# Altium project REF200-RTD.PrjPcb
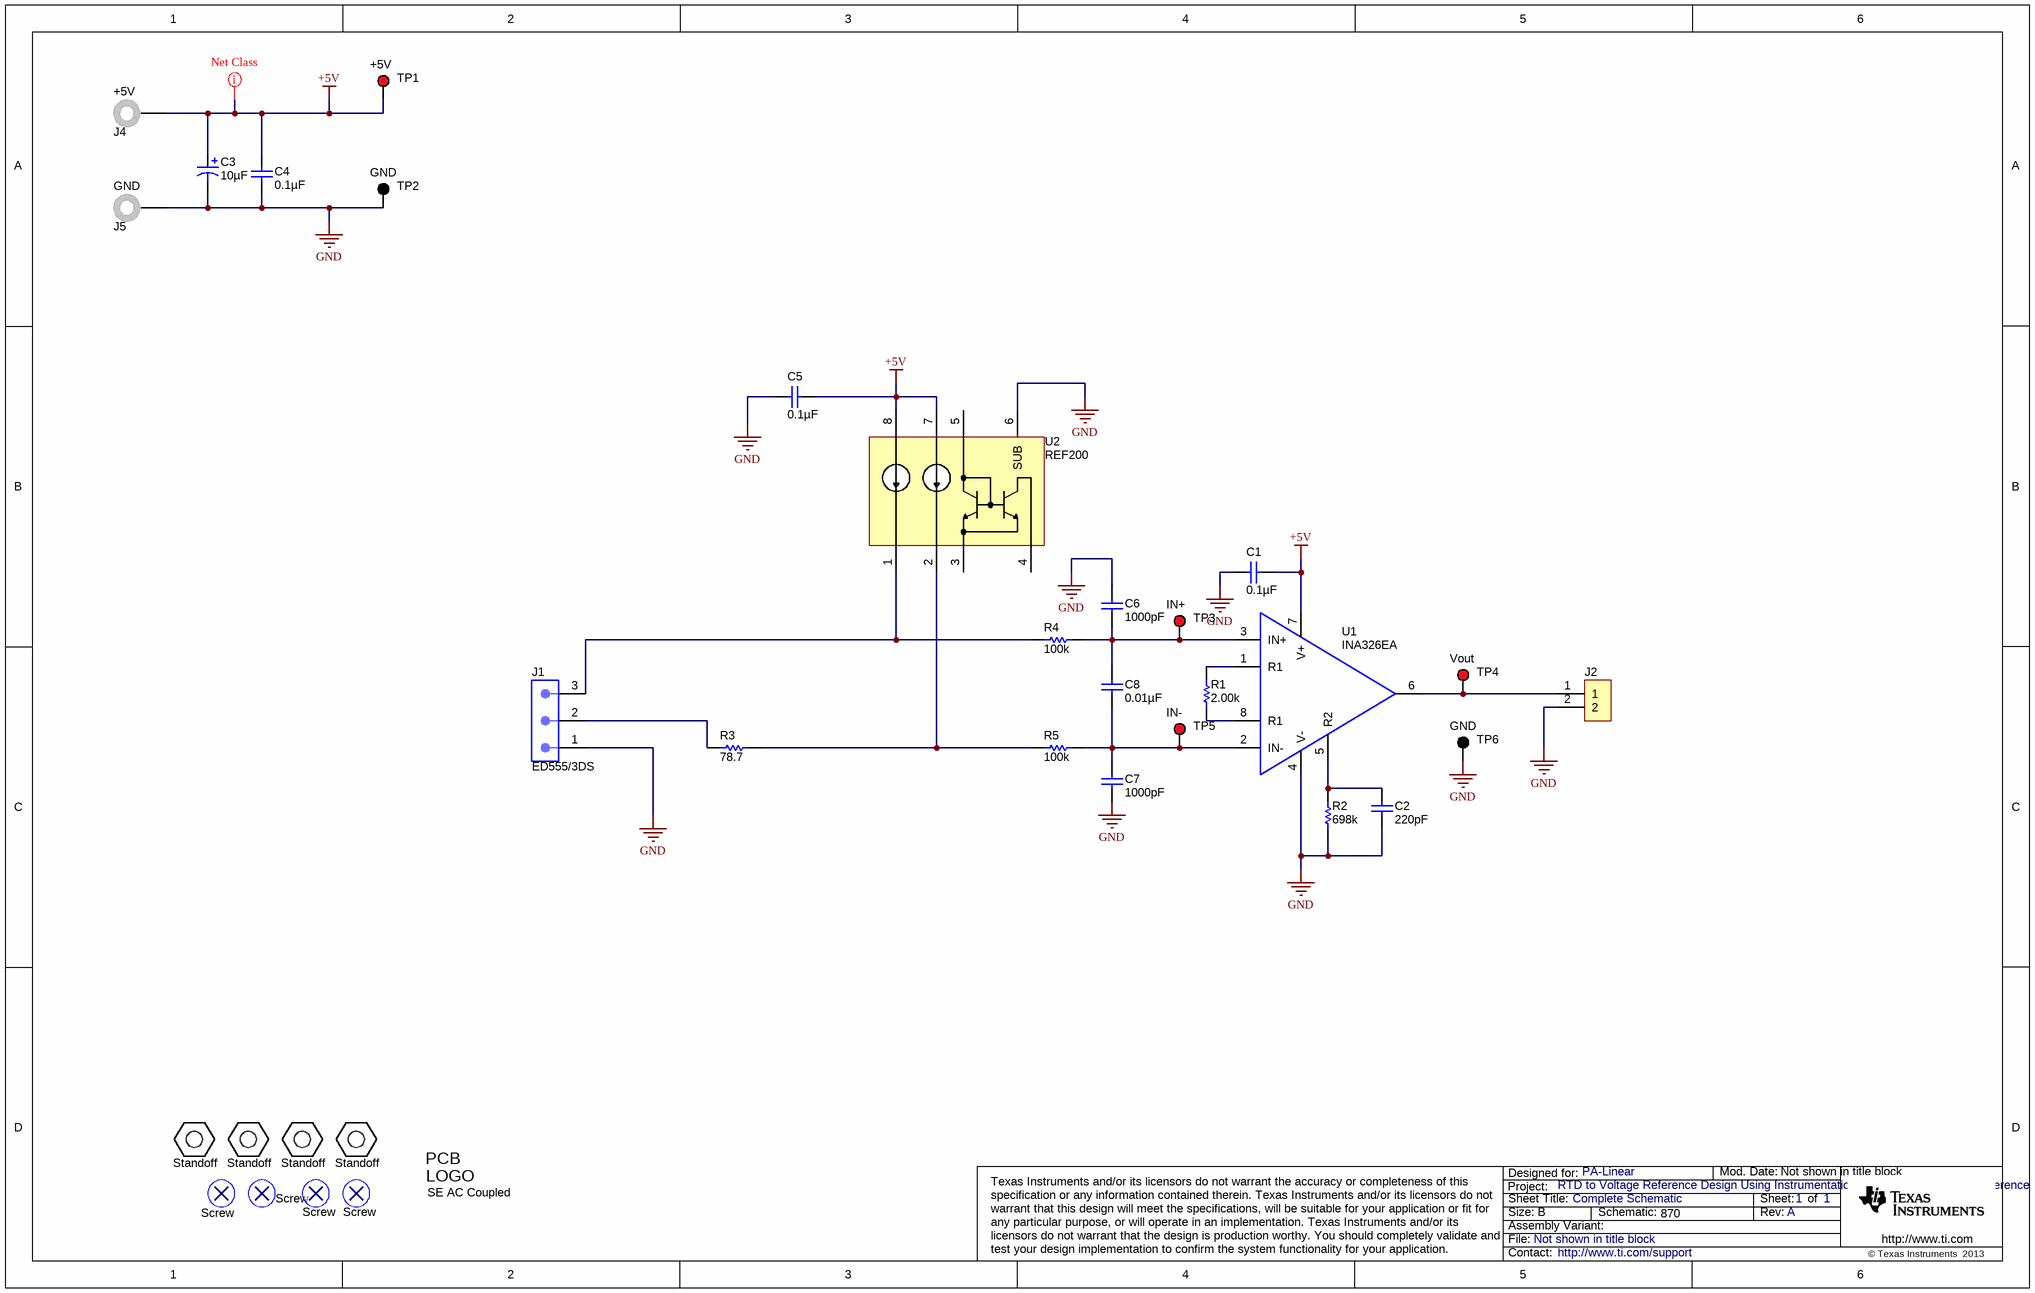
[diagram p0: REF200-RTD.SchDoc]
TechSupport: http://www.ti.com/support; SCH_Rev: A; PRJ_Title: RTD to Voltage Reference Design Using Instrumentation Amplifier and Current Reference; PRJ_Customer: PA-Linear; CopyrightYear: 2013
1 sheet, 34 parts. Net scope: global (net labels, ports and power ports of the same name join across sheets).
Board file: REF200-RTD.PcbDoc

## Sheet REF200-RTD.SchDoc: Complete Schematic
size B; Date: Not shown in title block; ApprovedBy: Not shown in title block; CheckedBy: Not shown in title block; Author: Not shown in title block; CompanyName: Not shown in title block; DrawnBy: Not shown in title block; Engineer: Not shown in title block; Organization: Not shown in title block; Address1: Not shown in title block; Address2: Not shown in title block; Address3: Not shown in title block; Address4: Not shown in title block; DocumentNumber: 1; Revision: Use project parameter SCH_Rev; SheetNumber: 1; SheetTotal: 1; PageSetup: Record=PageOptions¦CenterHorizontal=True¦CenterVertical=True¦PrintScale=0.69¦XCorrection=1.00¦YCorrection=1.00¦PrintKind=0¦BorderSize=5000000¦LeftOffset=0¦BottomOffset=0¦Orientation=2¦PaperLength=1000¦PaperWidth=1000¦Scale=100¦PaperSource=15¦PrintQuality=600¦MediaType=1¦DitherType=10¦PrintScaleMode=1¦PaperKind=Letter

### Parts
C1  ValueDisplayed: 0.1µF  [0603]  (hidden comment: 06033D104KAT2A)
C2  ValueDisplayed: 220pF  [0603]  (hidden comment: GRM1885C1H201JA01D)
C3  ValueDisplayed: 10µF  [7343-43]  (hidden comment: 293D106X9050E2TE3)
C4  ValueDisplayed: 0.1µF  [0603]  (hidden comment: 06033D104KAT2A)
C5  ValueDisplayed: 0.1µF  [0603]  (hidden comment: 06033D104KAT2A)
C6  ValueDisplayed: 1000pF  [0603]  (hidden comment: 06031C102JAT2A)
C7  ValueDisplayed: 1000pF  [0603]  (hidden comment: 06031C102JAT2A)
C8  ValueDisplayed: 0.01µF  [0603]  (hidden comment: 06031C103JAT2A)
J1  ED555/3DS  [Terminal Block 3.5mm 3 pos]
J2  Used in BOM report  [TERMINAL BLOCK 3.5MM 2 POS]  (value not drawn)
J4  +5V  [JACK NON-INSULATED .218"]
J5  GND  [JACK NON-INSULATED .218"]
R1  ValueDisplayed: 2.00k  [0603]  (hidden comment: CPF0603B2K0E)
R2  ValueDisplayed: 698k  [0603]  (hidden comment: CRCW0603698KFKEA)
R3  ValueDisplayed: 78.7  [0805_HV]  (hidden comment: CRCW080578R7FKEA)
R4  ValueDisplayed: 100k  [0603]  (hidden comment: CPF0603B100KE)
R5  ValueDisplayed: 100k  [0603]  (hidden comment: CPF0603B100KE)
TIPD191  SE AC Coupled  [TI_Symbol_Overlay_Small]  (no BOM)
TP1  +5V  [Keystone5005]
TP2  GND  [Keystone5006]
TP3  IN+  [Keystone5005]
TP4  Vout  [Keystone5005]
TP5  IN-  [Keystone5005]
TP6  GND  [Keystone5006]
U1  INA326EA  [VSSOP-8 (DGK) low density]
U2  REF200  [SOIC-8 (D) low density]
U3  Standoff  [MHOLE1]
U4  Standoff  [MHOLE1]
U5  Standoff  [MHOLE1]
U6  Standoff  [MHOLE1]
U7  Screw  (mechanical)
U8  Screw  (mechanical)
U9  Screw  (mechanical)
U10  Screw  (mechanical)

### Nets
+5V: C1.1 C3.1(+) C4.1 C5.1 J4.1 TP1.1 U1.7(V+) U2.7(I2_High) U2.8(I1_High)
GND: C1.2 C2.2 C3.2(-) C4.2 C5.2 C6.1 C7.2 J1.1 J2.2 J5.1 R2.1 TP2.1 TP6.1 U1.4(V-) U2.6(SUB)
NetC2_1: C2.1 R2.2 U1.5(R2)
NetC6_2: C6.2 C8.1 R4.2 TP3.1 U1.3(IN+)
NetC7_1: C7.1 C8.2 R5.2 TP5.1 U1.2(IN-)
NetJ1_2: J1.2 R3.1
NetJ1_3: J1.3 R4.1 U2.1(I1_Low)
NetJ2_1: J2.1 TP4.1 U1.6(OUT)
NetR1_1: R1.1 U1.8(R1)
NetR1_2: R1.2 U1.1(R1)
NetR3_2: R3.2 R5.1 U2.2(I2_Low)

Not connected (* = marked no-connect by the designer): U2 3(Mirror_Common) 4(Mirror_Out) 5(Mirror_In)

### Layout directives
net class Power: +5V

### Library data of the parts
C1 C4 C5 = 06033D104KAT2A: CAP, CERM, 0.1 µF, 25 V, +/- 10%, X5R, 0603; Manufacturer: AVX; Polarized: N; CompType: Capacitor; Value: 0.1uF; U/M: EA; Cap_F: 0.0000001; Tolerance_%: 10; ESR_ohm: 0.048; Value1: 0.048 ohm; VDC_V: 25; Value2: 25V; IRMS_A: 0.53; TaMin_C: -55; TaMax_C: 85
C2 = GRM1885C1H201JA01D: CAP, CERM, 200 pF, 50 V, +/- 5%, C0G/NP0, 0603; Manufacturer: MuRata; Polarized: N; CompType: Capacitor; Value: 200pF; U/M: EA; Cap_F: 0.0000000002; Tolerance_%: 5; Value1: Unknown; VDC_V: 50; Value2: 50V; TaMin_C: -55; TaMax_C: 125
C3 = 293D106X9050E2TE3: CAP, TA, 10 µF, 50 V, +/- 10%, 0.8 ohm, SMD; Manufacturer: Vishay-Sprague; Polarized: Y; CompType: Capacitor; Value: 10uF; U/M: EA; Cap_F: 0.00001; Tolerance_%: 10; Value1: 0.8 ohm; VDC_V: 50; Value2: 50V; ESR_ohm: 0.8; IRMS_A: 0.45; TaMin_C: -55; TaMax_C: 125; Cap_Case: E
C6 C7 = 06031C102JAT2A: CAP, CERM, 1000 pF, 100 V, +/- 5%, X7R, 0603; Manufacturer: AVX; Polarized: N; CompType: Capacitor; Value: 1000pF; U/M: EA; Cap_F: 0.000000001; Tolerance_%: 5; ESR_ohm: 0.276; Value1: 0.276 ohm; VDC_V: 100; Value2: 100V; TaMin_C: -55; TaMax_C: 125
C8 = 06031C103JAT2A: CAP, CERM, 0.01 µF, 100 V, +/- 5%, X7R, 0603; Manufacturer: AVX; Polarized: N; CompType: Capacitor; Value: 0.01uF; U/M: EA; Cap_F: 0.00000001; Tolerance_%: 5; ESR_ohm: 0.098; Value1: 0.098 ohm; VDC_V: 100; Value2: 100V; TaMin_C: -55; TaMax_C: 125
J1 = Screw Terminal, 3 Pos, 3.5mm Spacing, Through Hole: Manufacturer: On Shore Technology Inc; SymbolVersion: use current date i.e. 2008-05-20; SymbolCreator: Use LDAP id; CompType: Used in some BOM reports.  Useful for finding later.; U/M: EA, IN, or GM
J2 = Screw Terminal, 2 pos, 3.5mm, ED555/2DS: SymbolVersion: use current date i.e. 2008-05-20; SymbolCreator: Use a-id; CompType: Used in some BOM reports.  Useful for finding later.; U/M: EA, IN, or GM
J4 J5 = Banana Jack, Solder: JACK NON-INSULATED .218"; Manufacturer: Keystone; PartNumber: 575-4; SymbolVersion: use current date i.e. 2008-05-20; SymbolCreator: Use LDAP id; CompType: Used in some BOM reports.  Useful for finding later.; U/M: EA, IN, or GM
R1 = CPF0603B2K0E: RES, 2.00 k, 0.1%, 0.063 W, 0603; Manufacturer: TE Connectivity; CompType: Resistor; Value: 2.00k; Res_ohm: 2000; Value_Code: 2k00; Tolerance_%: 0.1; Power_W: 0.063; Value2: 0.063W; VDC_V: 50; TempCo: 25 ppm/C; EIA_Code: E192; U/M: EA
R2 = CRCW0603698KFKEA: RES, 698 k, 1%, 0.1 W, 0603; Manufacturer: Vishay-Dale; CompType: Resistor; Value: 698k; Res_ohm: 698000; Tolerance_%: 1; Power_W: 0.1; Value2: 0.1W; VDC_V: 75; TempCo: 100 ppm/C; EIA_Code: E96; U/M: EA
R3 = CRCW080578R7FKEA: RES, 78.7, 1%, 0.125 W, 0805; Manufacturer: Vishay-Dale; CompType: Resistor; Value: 78.7; Value_Code: 78R7; Tolerance_%: 1; Power_W: 0.125; Value2: 0.125W; VDC_V: 150; TempCo: 100 ppm/C; EIA_Code: E96; U/M: EA
R4 R5 = CPF0603B100KE: RES, 100 k, 0.1%, 0.063 W, 0603; Manufacturer: TE Connectivity; CompType: Resistor; Value: 100k; Res_ohm: 100000; Tolerance_%: 0.1; Power_W: 0.063; Value2: 0.063W; VDC_V: 50; TempCo: 25 ppm/C; EIA_Code: E192; U/M: EA
TIPD191 = TI_Logo: Texas Instrument Corporate Signature; SymbolCreator: codlsc
TP1 TP3-TP5 = 5005: Test Point, TH, Compact, Red; Manufacturer: Keystone; Alternate Manufacturer: Any; Alternate PartNumber: Equivalent; CompType: Test Point Loop; U/M: EA
TP2 TP6 = 5006: Test Point, TH, Compact, Black; Manufacturer: Keystone; Alternate Manufacturer: Any; Alternate PartNumber: Equivalent; CompType: Test Point Loop; U/M: EA
U1 = INA326EA: Precision, Rail-to-Rail I/O  INSTRUMENTATION AMPLIFIER, VSSOP-8; Manufacturer: Texas Instruments; SymbolVersion: use current date i.e. 2008-05-20; SymbolCreator: Use a-id; CompType: Used in some BOM reports.  Useful for finding later.; U/M: EA, IN, or GM
U2 = REF200: Manufacturer: Used in BOM report; SymbolVersion: use current date i.e. 2008-05-20; SymbolCreator: Use a-id; CompType: Used in some BOM reports.  Useful for finding later.; U/M: EA, IN, or GM
U3-U6 = Standoff, 1", 4-40, Alum, F-F: STANDOFF HEX 4-40THR ALUM 1"L; Manufacturer: Keystone; PartNumber: 2205; SymbolVersion: use current date i.e. 2008-05-20; SymbolCreator: Use LDAP id; CompType: Used in some BOM reports.  Useful for finding later.; U/M: EA, IN, or GM
U7-U10 = Machine Screw, 4-40, 0.25": MACHINE SCREW PAN PHILLIPS 4-40; Manufacturer: B&F Fastener Supply; PartNumber: PMSSS 440 0025 PH; SymbolVersion: use current date i.e. 2008-05-20; SymbolCreator: Use LDAP id; CompType: Mechanical; U/M: EA, IN, or GM

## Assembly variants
-100A: all parts fitted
